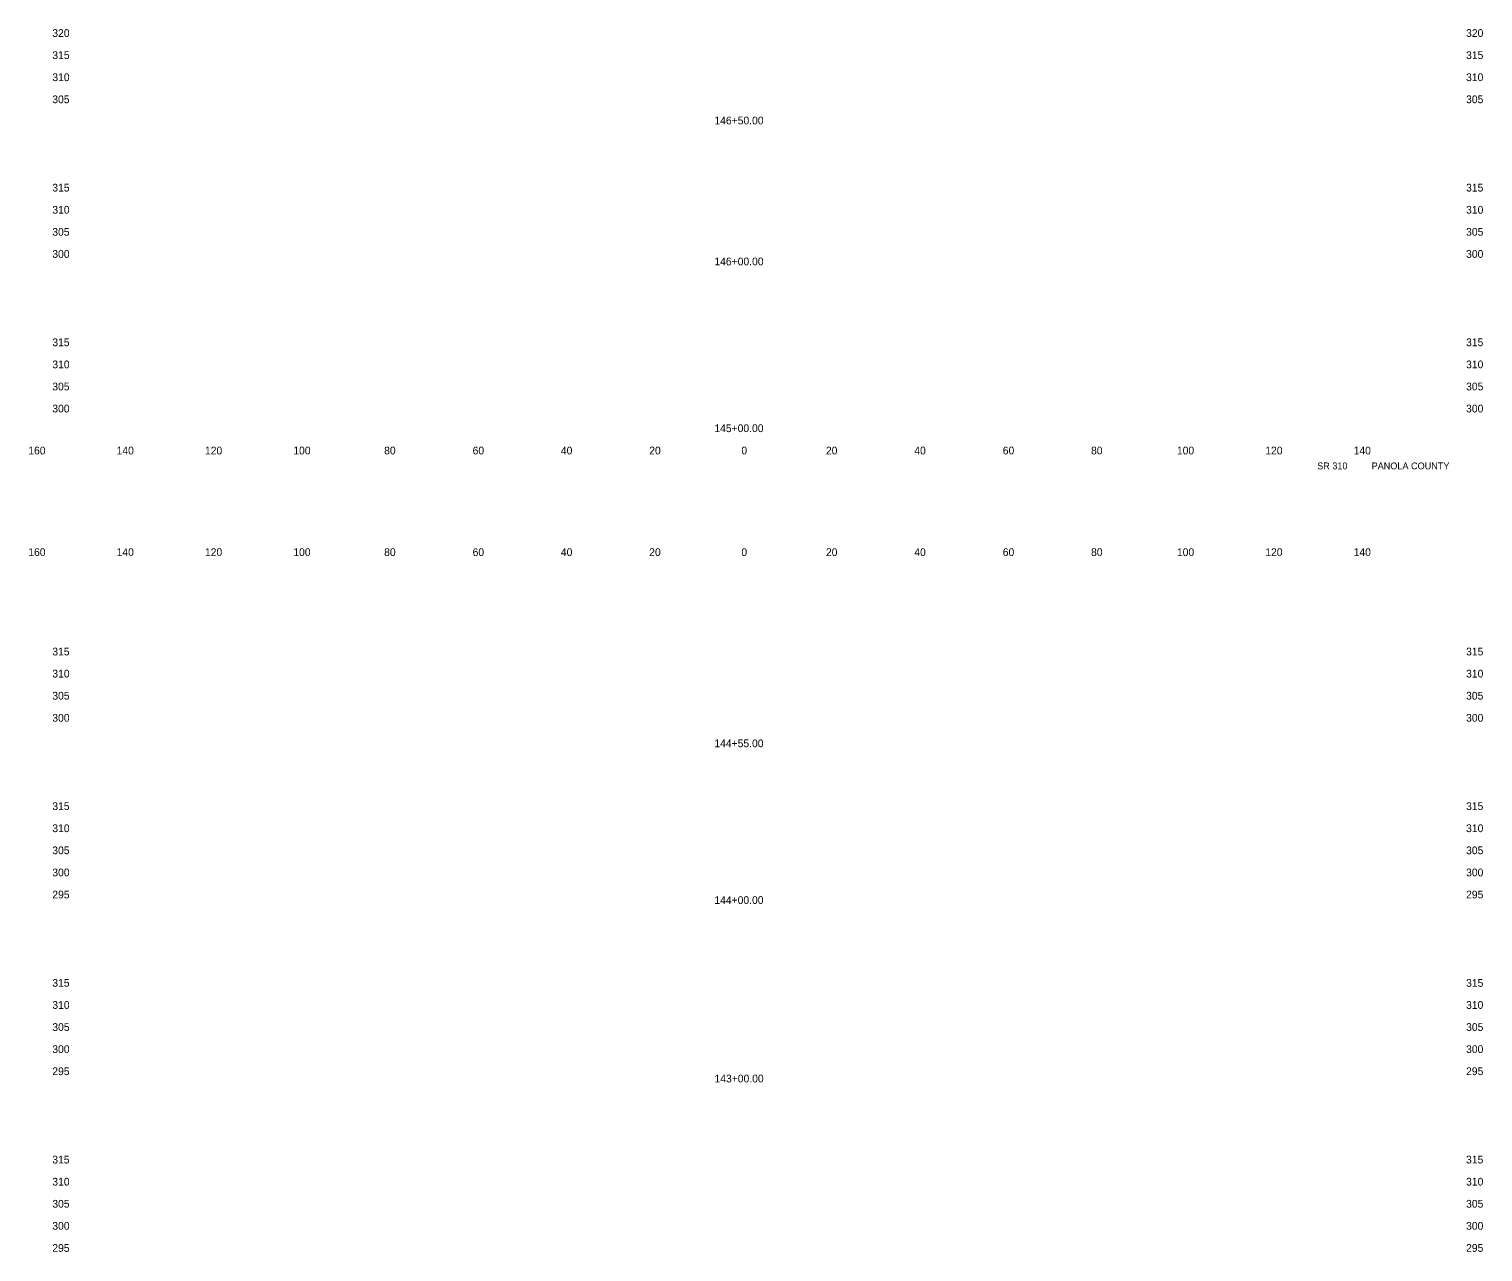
# Model space of a CAD drawing. Extents: x 21481 to 21810, y 6485 to 11067.
# Drawn here: x 21480.9 to 21809.9, y 10217.7 to 10494.5 of the extents above; entities that cross this region are included whole.
import ezdxf

# ---------------------------------------------------------------- set-up
doc = ezdxf.new("R2010")
doc.units = 0
for name, color, linetype in [('62', 7, 'Continuous'), ('XS_CELL', 7, 'Continuous'), ('XS_P_TX_DCH', 7, 'Continuous'), ('XS_P_TX_FS_BS', 7, 'Continuous')]:
    doc.layers.add(name, color=color, linetype=linetype)

msp = doc.modelspace()

# ---------------------------------------------------------------- texts
at = {"layer": '62'}
for s, p in [('  160  ', (21479.4, 10398.21)), ('  140  ', (21499.39, 10398.21)), ('  120  ', (21519.39, 10398.21)), ('  100  ', (21539.39, 10398.21)), ('  80  ', (21559.95, 10398.21)), ('  60  ', (21579.97, 10398.21)), ('  40  ', (21599.95, 10398.21)), ('  20  ', (21619.95, 10398.21)), ('  0  ', (21640.81, 10398.21)), ('  0  ', (21640.81, 10398.21)), ('  20  ', (21659.95, 10398.21)), ('  40  ', (21679.95, 10398.21)), ('  60  ', (21699.97, 10398.21)), ('  80  ', (21719.95, 10398.21)), ('  100  ', (21739.39, 10398.21)), ('  120  ', (21759.39, 10398.21)), ('  140  ', (21779.39, 10398.21)), ('  160  ', (21479.4, 10375.21)), ('  140  ', (21499.39, 10375.21)), ('  120  ', (21519.39, 10375.21)), ('  100  ', (21539.39, 10375.21)), ('  80  ', (21559.95, 10375.21)), ('  60  ', (21579.97, 10375.21)), ('  40  ', (21599.95, 10375.21)), ('  20  ', (21619.95, 10375.21)), ('  0  ', (21640.81, 10375.21)), ('  0  ', (21640.81, 10375.21)), ('  20  ', (21659.95, 10375.21)), ('  40  ', (21679.95, 10375.21)), ('  60  ', (21699.97, 10375.21)), ('  80  ', (21719.95, 10375.21)), ('  100  ', (21739.39, 10375.21)), ('  120  ', (21759.39, 10375.21)), ('  140  ', (21779.39, 10375.21))]:
    msp.add_text(s, height=1.75, dxfattribs=at).set_placement(p)
at = {"layer": 'XS_CELL'}
for s, p in [('  320  ', (21484.84, 10492.71)), ('  320  ', (21804.84, 10492.71)), ('  315  ', (21484.84, 10487.71)), ('  315  ', (21804.84, 10487.71)), ('  310  ', (21484.84, 10482.71)), ('  310  ', (21804.84, 10482.71)), ('  305  ', (21484.84, 10477.71)), ('  305  ', (21804.84, 10477.71)), ('  315  ', (21484.84, 10457.71)), ('  315  ', (21804.84, 10457.71)), ('  310  ', (21484.84, 10452.71)), ('  310  ', (21804.84, 10452.71)), ('  305  ', (21484.84, 10447.71)), ('  305  ', (21804.84, 10447.71)), ('  300  ', (21484.84, 10442.71)), ('  300  ', (21804.84, 10442.71)), ('  315  ', (21484.84, 10422.71)), ('  315  ', (21804.84, 10422.71)), ('  310  ', (21484.84, 10417.71)), ('  310  ', (21804.84, 10417.71)), ('  305  ', (21484.84, 10412.71)), ('  305  ', (21804.84, 10412.71)), ('  300  ', (21484.84, 10407.71)), ('  300  ', (21804.84, 10407.71)), ('  315  ', (21484.84, 10352.71)), ('  315  ', (21804.84, 10352.71)), ('  310  ', (21484.84, 10347.71)), ('  310  ', (21804.84, 10347.71)), ('  305  ', (21484.84, 10342.71)), ('  305  ', (21804.84, 10342.71)), ('  300  ', (21484.84, 10337.71)), ('  300  ', (21804.84, 10337.71)), ('  315  ', (21484.84, 10317.71)), ('  315  ', (21804.84, 10317.71)), ('  310  ', (21484.84, 10312.71)), ('  310  ', (21804.84, 10312.71)), ('  305  ', (21484.84, 10307.71)), ('  305  ', (21804.84, 10307.71)), ('  300  ', (21484.84, 10302.71)), ('  300  ', (21804.84, 10302.71)), ('  295  ', (21484.84, 10297.71)), ('  295  ', (21804.84, 10297.71)), ('  315  ', (21484.84, 10277.71)), ('  315  ', (21804.84, 10277.71)), ('  310  ', (21484.84, 10272.71)), ('  310  ', (21804.84, 10272.71)), ('  305  ', (21484.84, 10267.71)), ('  305  ', (21804.84, 10267.71)), ('  300  ', (21484.84, 10262.71)), ('  300  ', (21804.84, 10262.71)), ('  295  ', (21484.84, 10257.71)), ('  295  ', (21804.84, 10257.71)), ('  315  ', (21484.84, 10237.71)), ('  315  ', (21804.84, 10237.71)), ('  310  ', (21484.84, 10232.71)), ('  310  ', (21804.84, 10232.71)), ('  305  ', (21484.84, 10227.71)), ('  305  ', (21804.84, 10227.71)), ('  300  ', (21484.84, 10222.71)), ('  300  ', (21804.84, 10222.71)), ('  295  ', (21484.84, 10217.71)), ('  295  ', (21804.84, 10217.71))]:
    msp.add_text(s, height=1.75, dxfattribs=at).set_placement(p)
at = {"layer": 'XS_P_TX_DCH'}
for s, p in [('  146+50.00  ', (21634.7, 10472.92)), ('  146+00.00  ', (21634.7, 10441.01)), ('  145+00.00  ', (21634.69, 10403.26)), ('  144+55.00  ', (21634.69, 10331.93)), ('  144+00.00  ', (21634.69, 10296.45)), ('  143+00.00  ', (21634.72, 10256.06))]:
    msp.add_text(s, height=1.75, dxfattribs=at).set_placement(p)
at = {"layer": 'XS_P_TX_FS_BS'}
for s, p in [('SR 310', (21772.43, 10394.84)), ('SR 310', (21772.43, 10394.84)), ('SR 310', (21772.43, 10394.84)), ('PANOLA COUNTY', (21784.75, 10394.84)), ('PANOLA COUNTY', (21784.75, 10394.84)), ('PANOLA COUNTY', (21784.75, 10394.84))]:
    msp.add_text(s, height=1.54, dxfattribs=at).set_placement(p)

doc.saveas('drawing.dxf')
